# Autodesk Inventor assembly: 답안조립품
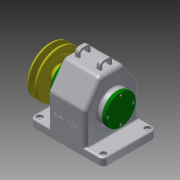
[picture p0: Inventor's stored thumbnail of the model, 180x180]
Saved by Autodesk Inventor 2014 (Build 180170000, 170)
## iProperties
Created: 2016-12
Part Number: 답안조립품
Document SubType Name: Assembly
Designer: USER
Author: USER
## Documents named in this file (14)
- C:\Users\USER\Desktop\461208V1020\답안조립품.iam
- C:\Users\USER\Desktop\461208V1020\본체.ipt
- C:\Users\USER\Desktop\461208V1020\앞커버.ipt
- C:\Users\USER\Desktop\461208V1020\뒤커버.ipt
- C:\Users\USER\Desktop\461208V1020\베어링 6203.ipt
- C:\Users\USER\Desktop\461208V1020\축.ipt
- C:\Users\USER\Desktop\461208V1020\키 - 6 x 6 x 22.ipt
- C:\Users\USER\Desktop\461208V1020\키 - 5 x 5 x 18.ipt
- C:\Users\USER\Desktop\461208V1020\스퍼기어.ipt
- C:\Users\USER\Desktop\461208V1020\부시.ipt
- C:\Users\USER\Desktop\461208V1020\V-벨트풀리.ipt
- C:\Users\USER\Desktop\461208V1020\멈춤나사 - M4x10.ipt
- C:\Users\USER\Desktop\461208V1020\볼트 M3 x 8.ipt
- C:\Users\USER\Desktop\461208V1020\볼트 M3 x 10.ipt
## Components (9 placed, 3 different names)
1. V-벨트풀리:1
2. ISO 4762 M3 x 8:1
3. ISO 4762 M3 x 8:2
4. ISO 4762 M3 x 8:3
5. ISO 4762 M3 x 8:4
6. ISO 4762 M3 x 10:1
7. ISO 4762 M3 x 10:2
8. ISO 4762 M3 x 10:3
9. ISO 4762 M3 x 10:4
